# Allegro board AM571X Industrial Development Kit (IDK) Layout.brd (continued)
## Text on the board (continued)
User.32: IMPEDANCE REQUIREMENT :- THIS DESIGN MAY NOT CONTAIN ALL THE FEATURES | NOTE : | LISTED IN THE ABOVE TABLE | CLASS 2 AND WORKMANSHIP SHALL CONFORM TO | IPC-A-600, CLASS 2. CURRENT REVISIONS. | 2. THE PWB SHALL BE FABRICATED TO IPC-6012, | 9. ALL VIAS TO HAVE SOLDERMASK. | 3. BOARD MATERIAL SHALL BE 180 Tg/350 Td ISOLA FR-370 HR | OR EQUIVALENT, RoHS COMPLIANT AND LEAD FREE | ASSEMBLY CAPABLE.  BOARD MATERIAL SHALL | MEET OR EXCEED IPC-4101B. COLOR: NATURAL. | 5. MINIMUM COPPER WALL THICKNESS OF PLATED-THRU | HOLES TO BE .001 INCH, WITH A MINIMUM | ANNULAR RING OF .002 INCH. | 4. BOARD MATERIAL & CONSTRUCTION TO BE UL94V0 CERTIFIED | AND MARKED ON TOP SIDE OF FINISHED BOARD. | FAB NOTES: | 6. OVERALL BOARD THICKNESS TO BE .0625 +/- 10% | AND APPLIES AFTER ALL LAMINATION AND PLATING | 1. ALL DIMENSIONS ARE IN INCHES, UNLESS | OTHERWISE NOTED. | SUPPLIED IPC-D-356 NETLIST. | PROCESSES, MEASURED FROM COPPER TO COPPER. | 8. BOARD MUST BE ELECTRICALLY TESTED USING | 7. MAX. WARP & TWIST TO BE .0075 INCHES PER INCH. | 2. APPLY LPI SOLDERMASK OVER BARE COPPER (SMOBC), | COLOR: BLACK SOLDERMASK SHALL | CONFORM TO IPC-SM-840, CLASS H. CURRENT REV. | 3. SOLDERMASK ARTWORK HAS ZERO (0) OVERSIZED PADS. | FABRICATION VENDOR IS ALLOWED TO ADJUST THE COMPONENT | SOLDERMASK PADS TO MEET THEIR TOOLING REQUIREMENTS. | 4. APPLY LPI SILKSCREEN OR EQUIVALENT PER THE ARTWORK. | IMMERSION GOLD, NICKEL 150 MICROINCHES THK MIN | GOLD 2-8 MICROINCHES THK MIN. | COLOR: WHITE. | PROCESS NOTES: | 1. PLATE ALL EXPOSED AREAS WITH ELECTROLESS
User.35: FIGURE | SIZE | 5.0 | 8.0 | DRILL CHART: L2_GND1 to L3_SIG1 | ALL UNITS ARE IN MILS | TOLERANCE | +2.0/-2.0 | PLATED | QTY | 518 | 612
User.36: FIGURE | SIZE | 5.0 | 8.0 | DRILL CHART: TOP to L2_GND1 | ALL UNITS ARE IN MILS | TOLERANCE | +2.0/-2.0 | PLATED | QTY | 518 | 612
User.39: FIGURE | SIZE | 8.0 | 10.0 | 30.0 | 33.0 | 35.04 | 36.0 | 40.0 | 43.0 | 45.0 | 50.0 | 67.0 | 69.0 | 79.0 | 91.0 | 120.0 | 140.0 | 33.46 | 47.0 | 59.0 | 68.9 | 125.98 | 138.0 | DRILL CHART: TOP to BOTTOM | ALL UNITS ARE IN MILS | TOLERANCE | +2.0/-2.0 | +3.0/-3.0 | PLATED | NON-PLATED | QTY | 761 | 1562 | 2 | 60 | 52 | 4 | 95 | 28 | 6 | 12 | 1
User.40: FIGURE | SIZE | 5.0 | 8.0 | DRILL CHART: L11_GND4 to BOTTOM | ALL UNITS ARE IN MILS | TOLERANCE | +2.0/-2.0 | PLATED | QTY | 363 | 447
User.41: FIGURE | SIZE | 8.0 | DRILL CHART: L3_SIG1 to L10_SIG4 | ALL UNITS ARE IN MILS | TOLERANCE | +2.0/-2.0 | PLATED | QTY | 920
User.42: FIGURE | SIZE | 5.0 | 8.0 | DRILL CHART: L10_SIG4 to L11_GND4 | ALL UNITS ARE IN MILS | TOLERANCE | +2.0/-2.0 | PLATED | QTY | 361 | 446
